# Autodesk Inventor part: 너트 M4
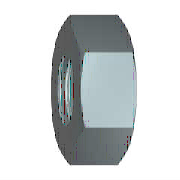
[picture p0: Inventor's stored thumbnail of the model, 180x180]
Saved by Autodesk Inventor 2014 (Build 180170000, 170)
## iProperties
Created: 2012-02
Part Number: 너트 M4
Material: 강철, 연강
Description: 6각 너트 및 6각 가는 너트 - 스타일 1
Document SubType Name: Modeling
Standard: KS B 1012
Designer: mduedu
Standards Organization: KS
Language: ko-KR
Size Designation: A M4
Categories: <MemberInstance><Categories><Category DisplayName="조임쇠" InternalName="e4da775c-781d-43d5-af7c-5136215cf5a6" Mnemonic="FSTN"><Category DisplayName="너트" InternalN
Density: 7.86 g/cm^3
Appearance: 강철
Mass: 0.846697 g
Surface Area: 1.71448 cm^2
Volume: 0.107722 cm^3
IsCustomPart: 0
Author: mduedu
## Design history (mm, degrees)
sketch "스케치1"
  geometry: L1 (-4.041, 0)-(-2.021, 3.5); L2 (-2.021, 3.5)-(2.021, 3.5); L3 (2.021, 3.5)-(4.041, 0); L4 (4.041, 0)-(2.021, -3.5); L5 (2.021, -3.5)-(-2.021, -3.5); L6 (-2.021, -3.5)-(-4.041, 0); 2 further points
  constraints: 12 end point, 1 coincident, 1 horizontal, 11 other
  dimensions: "d0" = 8.0829 distance of L3.end L1.start (= 1.1547 x SW)
extrude "본체" new body sketch "스케치1" distance "d1" = 3.2 (= KOH); taper "d2" = 0 deg
sketch "스케치2"
  geometry: L1 (0, 2.021)-(0, 4.041) reference; L2 (0, 4.041)-(3.2, 4.041) reference; L3 (3.2, 2.021)-(3.2, 4.041) reference; L4 (-0.64, 0)-(3.84, 0) reference; L5 (0.313, 4.041)-(0, 3.5); L6 (2.887, 4.041)-(3.2, 3.5)
  constraints: 4 end point, 4 point on line
  dimensions: "d3" = 30 deg angle of L1 L5 (= ANG1); "d4" = 30 deg angle of L3 L6 (= ANG2); "d5" = 7 diameter of L5.end L4 (= SW0); "d6" = 7 diameter of L6.end L4 (= SW01)
revolve "모따기1" sketch "스케치2" stored, may be unused: angle "d7" = 90 deg
sketch "스케치3"
  geometry: A1 r 3.5 centre (0, 0) between (-1.75, -3.031) and (1.75, -3.031) reference; 1 further point
  constraints: 1 coincident
hole "스레드" sketch "스케치3" at (0, 0) diameter "d25" = 3.242; stored, may be unused: countersink angle "d29" = 82 deg, drill point angle "d31" = 118 deg; dims "d26" = 6, "d27" = 4, "d28" = 2, "d30" = 8
workaxis "Work Axis1"
workplane "Work Plane1"
body "Solid1"
chamfer "모따기2" distance "d8" = 0.37889 (= -0.5 x GD1 + 0.5 x NND); stored, may be unused: angle "d9" = 30 deg, second distance "d40" = 0.37889 (= -0.5 x GD1 + 0.5 x NND)
chamfer "모따기3" distance "d10" = 0.37889 (= -0.5 x GD1 + 0.5 x NND); stored, may be unused: angle "d11" = 30 deg, second distance "d41" = 0.37889 (= -0.5 x GD1 + 0.5 x NND)
other parameters: "ANG1" = 30 deg [user parameter; used in 1 equation term], "ANG2" = 30 deg [user parameter; used in 1 equation term], "NND" = 4 [user parameter; used in 4 equation terms], "KOH" = 3.2 [user parameter; used in 1 equation term], "SW" = 7 [user parameter; used in 4 equation terms], "SW0" = 7 (= SW) [user parameter; used in 1 equation term], "SW01" = 7 (= SW) [user parameter; used in 1 equation term], "GD1" = 3.24223 (computed from THREADDIA, PTC, TOA) [user parameter; used in 4 equation terms], "d13" = 0, "d14" = 0, "d39" = 0, "d42" = 0, "GUL" = 0.37889 (= 0.541266 x PTC) [user parameter], "TPU" = 14.28571 (computed from PTC) [user parameter], "THREADDIA" = 4 [user parameter; used in 1 equation term], "TOA" = 30 deg [user parameter; used in 1 equation term], "PTC" = 0.7 [user parameter; used in 4 equation terms], "E0" = 8.085 (= 1.155 x SW) [user parameter], "GAL" = 0.37889 (= 0.541266 x PTC) [user parameter]
